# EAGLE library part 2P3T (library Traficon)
SLIDING SWITCH distributor: probably D'TRON
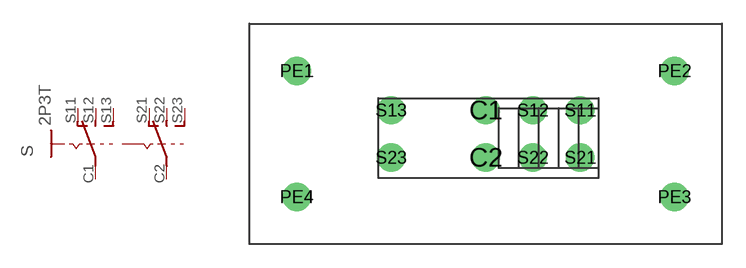
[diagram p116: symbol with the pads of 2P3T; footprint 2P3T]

Designator prefix S

## 2P3T  [2P3T]
C1  S1  pas
C2  S2  pas
S11  S11  pas
S12  S12  pas
S13  S13  pas
S21  S21  pas
S22  S22  pas
S23  S23  pas

## Footprint 2P3T (pad centres in mm)
TOGGLE SWITCH distributor RS Components
drill 1.2 round: C1 3,0.5; C2 3,-2.5; PE1 -9,3; PE2 15,3; PE3 15,-5; PE4 -9,-5; S11 9,0.5; S12 6,0.5; S13 -3,0.5; S21 9,-2.5; S22 6,-2.5; S23 -3,-2.5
